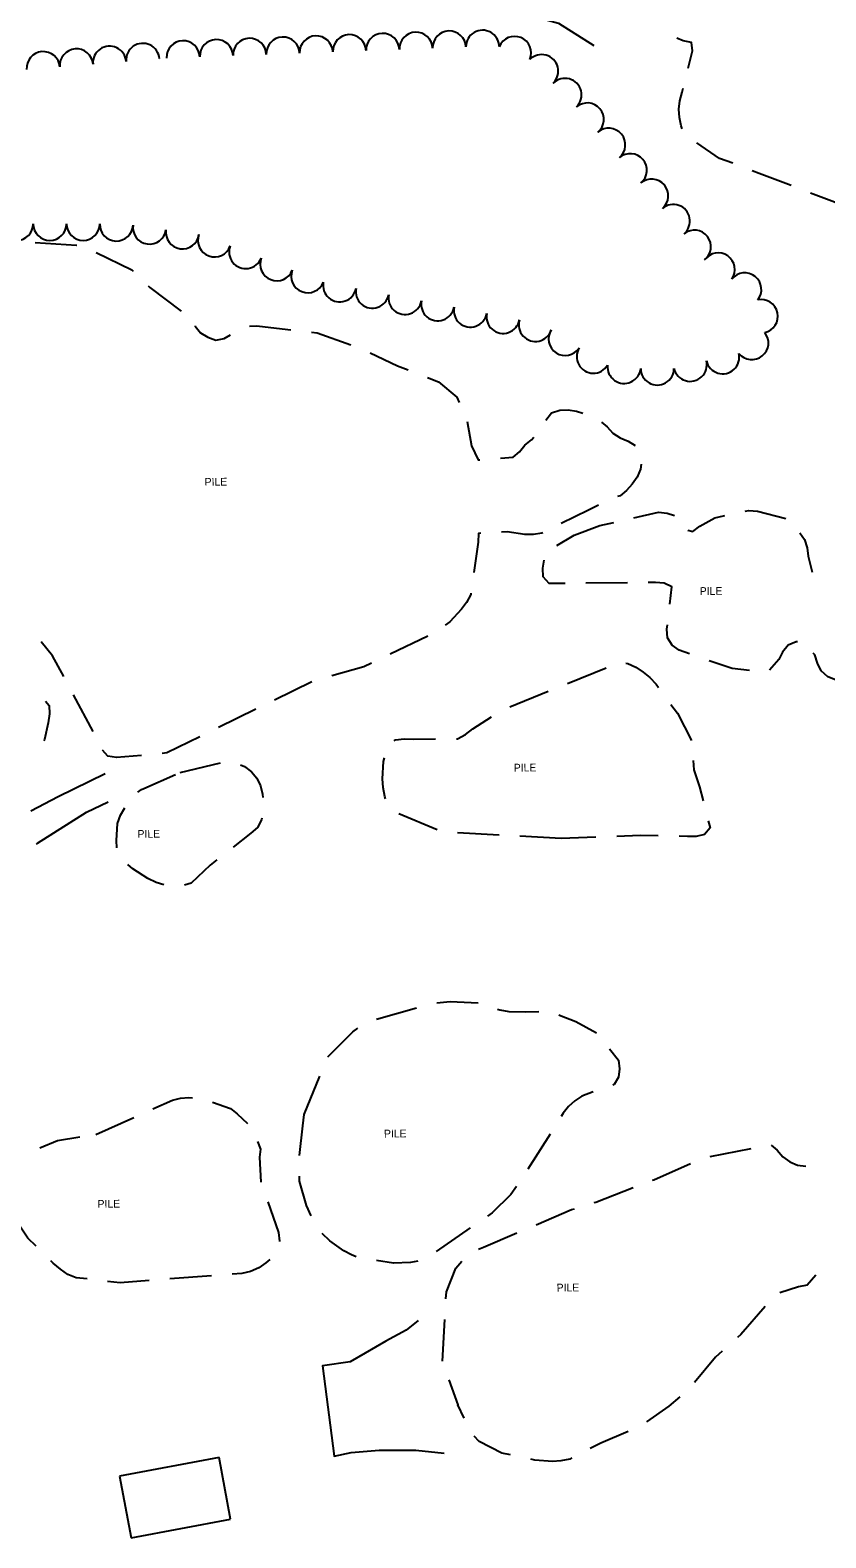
# Model space of a CAD drawing. Extents: x -2233 to 187241, y 4582 to 150524.
# Drawn here: x 104072 to 104550, y 57288 to 58194 of the extents above; entities that cross this region are included whole.
import ezdxf

# ---------------------------------------------------------------- set-up
doc = ezdxf.new("R2010")
doc.units = 0
for name, color, linetype in [('BLDG', 7, 'Continuous'), ('DRIVWY', 7, 'Continuous'), ('TREES', 7, 'Continuous'), ('WALL', 7, 'Continuous')]:
    doc.layers.add(name, color=color, linetype=linetype)

msp = doc.modelspace()

# ---------------------------------------------------------------- linework, layer by layer
at = {"layer": 'BLDG'}
for p, q in [((104388.8, 57883.92), (104399.15, 57890.22)), ((104431.2, 57861.54), (104406.2, 57861.29)), ((104311.15, 57829.48), (104288.6, 57818.7)), ((104395.19, 57801), (104418.36, 57810.37)), ((104241.61, 57802.08), (104219.17, 57791.08)), ((104360.42, 57786.92), (104383.6, 57796.31)), ((104110.1, 57772.09), (104098.32, 57794.14)), ((104207.95, 57785.57), (104185.49, 57774.58)), ((104162.34, 57747.55), (104186.68, 57753.26)), ((104316.81, 57713.08), (104293.79, 57722.81)), ((104354, 57709.89), (104329.04, 57711.26)), ((104391.44, 57707.85), (104366.48, 57709.21)), ((104412.23, 57708.66), (104391.44, 57707.85)), ((104280.44, 57599.28), (104304.47, 57606.18)), ((104236.9, 57542.03), (104246.36, 57565.17)), ((104111.79, 57530.14), (104134.6, 57540.37)), ((104384.67, 57530.37), (104371.41, 57509.19)), ((104480.89, 57516.76), (104505.42, 57521.59)), ((104336.76, 57473.94), (104316.23, 57459.69)), ((104181.15, 57445.24), (104156.22, 57443.3)), ((104319.98, 57393.94), (104321.42, 57418.91)), ((104185.81, 57335.95), (104125.98, 57324.74)), ((104192.74, 57298.98), (104185.81, 57335.95)), ((104125.98, 57324.74), (104132.91, 57287.77)), ((104132.91, 57287.77), (104192.74, 57298.98))]:
    msp.add_line(p, q, dxfattribs=at)
for points in [[(104467.69, 58170.74), (104470.27, 58181.04), (104469.64, 58186.14), (104464.66, 58187.17), (104460.79, 58188.68)], [(104464.14, 58134.15), (104463.44, 58135.98), (104462.39, 58140.95), (104462.05, 58146.05), (104462.72, 58151.09), (104464.03, 58156.22), (104464.63, 58158.63)], [(104494.45, 58113.54), (104486.45, 58116.49), (104472.9, 58125.86)], [(104529.46, 58100.09), (104510.36, 58107.37), (104506.12, 58109.07)], [(104564, 58085.64), (104555.58, 58090.12), (104541.13, 58095.63)], [(104075.36, 58065.93), (104100.2, 58064.32), (104100.3, 58064.29)], [(104112.02, 58059.99), (104133.38, 58049.47), (104134.27, 58048.68)], [(104143.15, 58039.94), (104144.28, 58039), (104163, 58024.75)], [(104171.38, 58015.83), (104171.43, 58015.73), (104174.7, 58011.73), (104179.12, 58009.11), (104183.81, 58007.36), (104188.91, 58008.34), (104192.7, 58010.54)], [(104204.01, 58015.71), (104208.42, 58015.87), (104213.46, 58015.28), (104228.86, 58013.48)], [(104241.28, 58012.03), (104244.73, 58011.63), (104265.05, 58004.53)], [(104276.54, 57999.65), (104293.07, 57991.81), (104299.32, 57989.38)], [(104310.96, 57984.84), (104317.57, 57982.27), (104328.74, 57973.02), (104330.06, 57969.87)], [(104334.77, 57958.31), (104337.37, 57943.81), (104341.41, 57935.43), (104342.38, 57935.47)], [(104382.06, 57959.12), (104385.54, 57963.58), (104390.57, 57965.13), (104395.6, 57965.33), (104400.64, 57964.59), (104404.41, 57963.41)], [(104415.66, 57958.05), (104418.95, 57955.12), (104422.37, 57951.34), (104426.85, 57948.58), (104431.63, 57946.54), (104435.91, 57943.9)], [(104354.85, 57936.31), (104362.41, 57936.94), (104366.34, 57940.21), (104369.47, 57944.27), (104373.54, 57947.48), (104374.86, 57948.96)], [(104439.34, 57932.71), (104438.92, 57929.77), (104437.02, 57925.01), (104434.04, 57920.8), (104430.55, 57916.95), (104426.7, 57913.75), (104425.23, 57913.26)], [(104413.84, 57908.18), (104407.85, 57905.21), (104391.44, 57897.08)], [(104435.11, 57900.58), (104449.82, 57903.9), (104454.94, 57903.37), (104459.51, 57902)], [(104501.96, 57904.48), (104504.08, 57904.94), (104509.41, 57904.56), (104526.31, 57900.06)], [(104399.15, 57890.22), (104414.49, 57895.92), (104422.92, 57897.82)], [(104467.43, 57893.21), (104470.45, 57892.3), (104474.59, 57895.5), (104483.75, 57900.63), (104488.92, 57901.69), (104489.73, 57901.87)], [(104342.99, 57891.24), (104341.71, 57891.17), (104341.55, 57885.92), (104338.93, 57867.65)], [(104380.24, 57891.53), (104379.7, 57891.26), (104374.75, 57890.49), (104369.57, 57890.52), (104358.89, 57892.06), (104355.48, 57891.88)], [(104534.83, 57891.47), (104537.57, 57887.42), (104539.13, 57882.54), (104539.76, 57877.51), (104542.13, 57867.88)], [(104393.7, 57861.17), (104384.04, 57861.07), (104380.61, 57865.07), (104380.28, 57870.25), (104381.1, 57875.06)], [(104456.65, 57848.71), (104457.75, 57859.06), (104453.27, 57861.33), (104447.93, 57861.71), (104443.7, 57861.66)], [(104337.15, 57855.27), (104337.03, 57854.42), (104334.56, 57849.72), (104331.43, 57845.73), (104324.45, 57838.03), (104321.73, 57836.05)], [(104468.54, 57818.78), (104462.16, 57820.97), (104458.02, 57824.1), (104455.17, 57828.53), (104454.91, 57833.56), (104455.26, 57836.29)], [(104092.42, 57805.15), (104085.79, 57817.55), (104078.84, 57826)], [(104533.38, 57826.03), (104532.49, 57826.13), (104527.68, 57824.06), (104524.35, 57819.92), (104522.09, 57815.44), (104516.5, 57808.99)], [(104277.33, 57813.3), (104272.76, 57811.11), (104253.59, 57805.63)], [(104430.23, 57813.15), (104431.43, 57813.03), (104436.28, 57810.78), (104440.69, 57807.87), (104444.68, 57804.53), (104448.33, 57800.61), (104449.87, 57798.52)], [(104504.5, 57808.74), (104494.15, 57809.98), (104480.36, 57814.72)], [(104559.15, 57802.91), (104556.25, 57803.18), (104551.48, 57805.08), (104547.49, 57808.71), (104545.28, 57813.3), (104543.73, 57818.17), (104542.86, 57819.21)], [(104081.5, 57790.3), (104083.78, 57787.88), (104083.98, 57782.77), (104083.16, 57777.43), (104080.89, 57767.33), (104080.45, 57766.66)], [(104457.33, 57788.49), (104461.23, 57783.24), (104469.72, 57766.85)], [(104328.37, 57767.83), (104329.04, 57767.84), (104333.82, 57770.4), (104338.33, 57773.76), (104349.52, 57780.91)], [(104174.27, 57769.07), (104154.44, 57759.35), (104151.55, 57758.95)], [(104139.11, 57757.82), (104124.11, 57756.61), (104118.99, 57757.42), (104115.82, 57760.99)], [(104291.07, 57766.59), (104291.9, 57767.11), (104297.01, 57767.74), (104302.55, 57767.58), (104315.87, 57767.71)], [(104198.75, 57752.16), (104201.02, 57751.18), (104205.23, 57747.98), (104208.43, 57744.05), (104210.71, 57739.46), (104211.98, 57734.45), (104212.18, 57732.59)], [(104285.88, 57731.68), (104285.33, 57733.16), (104284.41, 57738.47), (104284.08, 57743.78), (104284.62, 57754.09), (104285.25, 57756.4)], [(104470.63, 57754.7), (104471.06, 57749.23), (104474.4, 57738.98), (104476.61, 57730.52)], [(104136.89, 57735.77), (104139.27, 57737.25), (104140.55, 57737.84), (104159.54, 57746.31)], [(104124.45, 57702.21), (104124.09, 57706.74), (104124.85, 57716.88), (104126.6, 57721.87), (104129.07, 57726.22)], [(104211.46, 57720.21), (104211.2, 57719.11), (104208.87, 57714.41), (104204.94, 57711.12), (104194.34, 57702.77)], [(104479.75, 57718.43), (104480.84, 57714.28), (104477.57, 57710.21), (104472.4, 57709.09), (104467.35, 57709.18), (104462.2, 57709.28)], [(104449.7, 57709.5), (104438.85, 57709.69), (104424.71, 57709.14)], [(104152.65, 57680.16), (104148.01, 57681.56), (104143.03, 57683.82), (104133.97, 57689.63), (104130.98, 57692.18)], [(104184.52, 57695.03), (104180.44, 57691.82), (104168.97, 57681.12), (104165.03, 57679.91)], [(104316.55, 57609.27), (104324.61, 57610.04), (104341.49, 57609.26)], [(104353.16, 57605.41), (104354.53, 57604.93), (104359.94, 57603.98), (104370.16, 57603.79), (104377.99, 57603.91)], [(104390.04, 57601.97), (104390.33, 57601.84), (104400.15, 57597.97), (104412.52, 57591.16)], [(104251.2, 57576.66), (104266.07, 57591.83), (104269.17, 57593.96)], [(104420.43, 57581.57), (104425.79, 57574.69), (104426.41, 57569.59), (104425.88, 57564.55), (104423.27, 57560.05), (104422.47, 57559.71)], [(104146.01, 57545.49), (104157.72, 57550.74), (104162.69, 57551.88), (104167.71, 57552.28), (104169.73, 57552.17)], [(104410.66, 57555.74), (104403.69, 57553.1), (104399.48, 57550.39), (104395.69, 57546.9), (104392.56, 57542.98), (104391.3, 57540.97)], [(104181.87, 57549.47), (104192.61, 57545.62), (104196.74, 57542.56), (104202.89, 57536.77)], [(104234.16, 57517.43), (104236.03, 57535.26), (104236.9, 57542.03)], [(104078.19, 57522.1), (104088.65, 57526.39), (104102.17, 57528.58)], [(104208.88, 57525.95), (104210.69, 57521.33), (104210.1, 57516.36), (104210.82, 57501.35)], [(104517.6, 57523.68), (104521.18, 57520.58), (104524.53, 57516.72), (104528.8, 57513.67), (104533.43, 57511.7), (104538.28, 57511.11)], [(104446.25, 57502.66), (104446.93, 57502.93), (104469.15, 57512.7)], [(104241.14, 57481.15), (104238.31, 57487.42), (104234.2, 57502.06), (104234.03, 57504.97)], [(104364.42, 57498.83), (104361.17, 57494.1), (104349.97, 57483.05), (104347.05, 57481.04)], [(104411.25, 57489.19), (104412.24, 57489.49), (104434.59, 57498.15)], [(104215.01, 57489.58), (104221.55, 57471.28), (104222.11, 57465.95), (104222.06, 57465.74)], [(104075.81, 57462.9), (104070.89, 57467.7), (104060.84, 57482.79)], [(104376.25, 57475.89), (104397.46, 57484.95), (104399.3, 57485.52)], [(104268.18, 57456.67), (104265.3, 57457.82), (104260.74, 57460.22), (104252.34, 57466.11), (104247.75, 57470.7)], [(104341.77, 57461.14), (104344.7, 57462.41), (104364.75, 57470.98)], [(104106.44, 57443.27), (104099.83, 57444.03), (104094.92, 57446.06), (104090.43, 57449.11), (104086.15, 57452.82), (104084.75, 57454.17)], [(104216.3, 57455.04), (104213.96, 57452.92), (104209.68, 57450.07), (104204.72, 57447.86), (104199.55, 57446.67), (104193.61, 57446.2)], [(104305.2, 57454.08), (104300.75, 57453.2), (104290.6, 57452.81), (104280.41, 57454.35)], [(104322.13, 57431.38), (104322.38, 57435.57), (104328.13, 57449.87), (104331.61, 57454)], [(104143.76, 57442.33), (104126.42, 57440.98), (104118.85, 57441.84)], [(104544.39, 57445.53), (104539.1, 57439.57), (104533.86, 57438.58), (104522.71, 57435.04)], [(104514.01, 57426.84), (104499.31, 57409.89), (104497.4, 57408.18)], [(104488.08, 57399.84), (104484.18, 57396.35), (104471.56, 57381.14)], [(104333.05, 57359.76), (104329.3, 57367.62), (104329.52, 57367.63), (104324.05, 57382.73)], [(104462.67, 57372.43), (104455.98, 57366.85), (104442.71, 57357.39)], [(104431.66, 57351.71), (104415.1, 57344.71), (104408.86, 57341.49)], [(104360.89, 57337.61), (104355.71, 57338.73), (104342.11, 57345.66), (104339, 57348.83)], [(104397.75, 57335.76), (104396.49, 57335.11), (104391.24, 57334.04), (104386.14, 57333.71), (104375.62, 57334.4), (104373.11, 57334.95)]]:
    msp.add_lwpolyline(points, dxfattribs=at)
at = {"layer": 'DRIVWY'}
for points in [[(104365.57, 58203.15), (104372.04, 58202.52), (104389.72, 58197.73), (104411.03, 58184.31)], [(104117.35, 57746.68), (104089.07, 57732.87), (104072.68, 57724.25)], [(104076.1, 57704.56), (104076.67, 57705.11), (104106.07, 57723.68), (104119.1, 57729.87)]]:
    msp.add_lwpolyline(points, dxfattribs=at)
at = {"layer": 'TREES'}
for centre, radius, start, end in [((104139.94, 58175.59), 10, 4.7418, 184.7418), ((104164.21, 58177.14), 10, 2.10613, 182.10613), ((104184.2, 58177.87), 10, 2.10613, 182.10613), ((104204.19, 58178.61), 10, 2.10613, 182.10613), ((104224.17, 58179.34), 10, 2.10613, 182.10613), ((104244.16, 58180.08), 10, 2.10613, 182.10613), ((104264.15, 58180.81), 10, 2.10613, 182.10613), ((104284.13, 58181.55), 10, 2.10613, 182.10613), ((104304.12, 58182.28), 10, 2.10613, 182.10613), ((104324.11, 58183.02), 10, 2.10613, 182.10613), ((104344.1, 58183.49), 10, 0.57101, 180.57101), ((104363.34, 58179.76), 10, 337.54041, 157.54041), ((104080.15, 58170.64), 10, 4.66571, 184.66571), ((104100.08, 58172.28), 10, 4.74139, 184.74139), ((104120.01, 58173.93), 10, 4.7418, 184.7418), ((104149.91, 58176.41), 0.000000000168, 4.2314, 184.2314), ((104379.6, 58168.82), 10, 314.54292, 134.54292), ((104393.62, 58154.56), 10, 314.51797, 134.51797), ((104407.05, 58139.84), 9.94, 310.20197, 130.20197), ((104419.92, 58124.6), 10, 310.20197, 130.20197), ((104432.83, 58109.33), 10, 310.20197, 130.20197), ((104445.74, 58094.05), 10, 310.20197, 130.20197), ((104458.71, 58078.83), 10, 310.62455, 130.62455), ((104064.13, 58077.13), 10, 180.06302, 0.06302), ((104084.13, 58077.15), 10, 180.06302, 0.06302), ((104104.13, 58077.18), 10, 180.06302, 0.06302), ((104124.12, 58076.81), 10, 177.81955, 357.81955), ((104144.01, 58074.98), 10, 171.69915, 351.69915), ((104163.8, 58072.09), 10, 171.69915, 351.69915), ((104183.1, 58067.26), 10, 160.16629, 340.16629), ((104471.37, 58063.35), 10, 307.9451, 127.9451), ((104201.83, 58060.24), 10, 158.71721, 338.71721), ((104485.69, 58049.71), 10, 324.84929, 144.84929), ((104220.46, 58052.96), 10, 158.64436, 338.64436), ((104239.11, 58045.74), 10, 158.9916, 338.9916), ((104258.26, 58040.26), 10, 169.09309, 349.09309), ((104501.66, 58037.68), 10, 321.16277, 141.16277), ((104277.9, 58036.48), 10, 169.09309, 349.09309), ((104297.54, 58032.69), 10, 169.09309, 349.09309), ((104317.18, 58028.91), 10, 169.09309, 349.09309), ((104511.57, 58021.63), 10, 282.2525, 102.2525), ((104336.82, 58025.12), 10, 169.09309, 349.09309), ((104356.46, 58021.34), 10, 169.09309, 349.09309), ((104375.83, 58016.48), 10, 162.75988, 342.75988), ((104393.76, 58008.06), 10, 146.9011, 326.9011), ((104505.9, 58005.6), 10, 218.78731, 38.78731), ((104410.69, 57997.42), 10, 148.79241, 328.79241), ((104468.89, 57992.52), 10, 192.99192, 12.99192), ((104488.37, 57997.05), 10, 193.20223, 13.20223), ((104429.19, 57991.27), 10, 174.45134, 354.45134), ((104449.14, 57990.28), 10, 179.90989, 359.90989)]:
    msp.add_arc(centre, radius, start, end, dxfattribs=at)
at = {"layer": 'WALL'}
msp.add_lwpolyline([(104305.35, 57418.34), (104298.21, 57412.52), (104285.96, 57405.84), (104273.66, 57398.67), (104264.49, 57393.47), (104247.96, 57391.01), (104255.05, 57336.74), (104265.1, 57339.06), (104282, 57340.53), (104304.03, 57340.38), (104320.95, 57338.61)], dxfattribs=at)

# ---------------------------------------------------------------- texts
at = {"layer": 'BLDG'}
for p in [(104177.13, 57919.78), (104474.64, 57854.19), (104362.91, 57748.09), (104136.81, 57708.3), (104284.9, 57528.25), (104112.81, 57486.04), (104388.66, 57435.72)]:
    msp.add_text('PILE', height=4.68, rotation=0.5, dxfattribs=at).set_placement(p)

doc.saveas('drawing.dxf')
